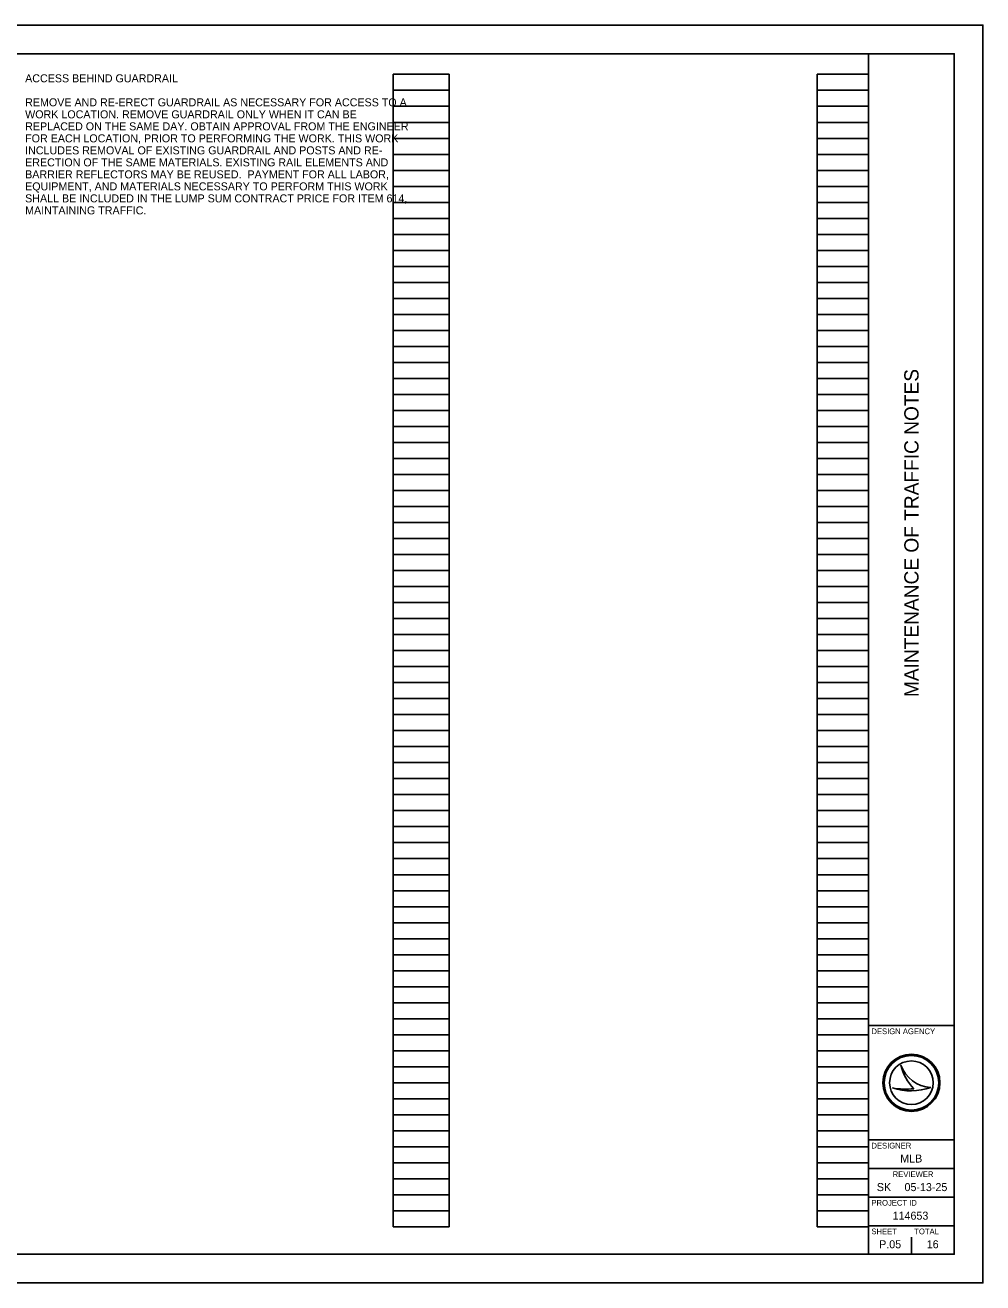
# Model space of a CAD drawing. Extents: x 0 to 34, y 0 to 22.
# Drawn here: x 17.24 to 34, y 0 to 22 of the extents above; entities that cross this region are included whole.
import ezdxf

# ---------------------------------------------------------------- set-up
doc = ezdxf.new("R2010")
doc.units = 0
for name, color, linetype in [('SH_Border', 7, 'Continuous'), ('SH_Cut_Line', 7, 'Continuous'), ('SH_Data', 7, 'Continuous'), ('SH_Text', 7, 'Continuous')]:
    doc.layers.add(name, color=color, linetype=linetype)

msp = doc.modelspace()

# ---------------------------------------------------------------- linework, layer by layer
at = {"layer": 'SH_Border'}
for p, q in [((32, 0.5), (32, 21.5)), ((32, 4.5), (33.5, 4.5)), ((32, 2.5), (33.5, 2.5)), ((32, 2), (33.5, 2)), ((32, 1.5), (33.5, 1.5)), ((32, 1), (33.5, 1))]:
    msp.add_line(p, q, dxfattribs=at)
msp.add_lwpolyline([(1.5, 21.5), (33.5, 21.5), (33.5, 0.5), (1.5, 0.5)], close=True, dxfattribs=at)
at = {"layer": 'SH_Cut_Line'}
msp.add_lwpolyline([(0, 0), (34, 0), (34, 22), (0, 22)], close=True, dxfattribs=at)
at = {"layer": 'SH_Data'}
for p, q in [((23.68, 0.98), (23.68, 21.14)), ((23.68, 21.14), (24.66, 21.14)), ((24.66, 0.98), (24.66, 21.14)), ((31.1, 0.98), (31.1, 21.14)), ((31.1, 21.14), (32, 21.14)), ((32, 0.98), (32, 21.14)), ((23.68, 20.86), (24.66, 20.86)), ((31.1, 20.86), (32, 20.86)), ((23.68, 20.58), (24.66, 20.58)), ((31.1, 20.58), (32, 20.58)), ((23.68, 20.3), (24.66, 20.3)), ((31.1, 20.3), (32, 20.3)), ((23.68, 20.02), (24.66, 20.02)), ((31.1, 20.02), (32, 20.02)), ((23.68, 19.74), (24.66, 19.74)), ((31.1, 19.74), (32, 19.74)), ((23.68, 19.46), (24.66, 19.46)), ((31.1, 19.46), (32, 19.46)), ((23.68, 19.18), (24.66, 19.18)), ((31.1, 19.18), (32, 19.18)), ((23.68, 18.9), (24.66, 18.9)), ((31.1, 18.9), (32, 18.9)), ((23.68, 18.62), (24.66, 18.62)), ((31.1, 18.62), (32, 18.62)), ((23.68, 18.34), (24.66, 18.34)), ((31.1, 18.34), (32, 18.34)), ((23.68, 18.06), (24.66, 18.06)), ((31.1, 18.06), (32, 18.06)), ((23.68, 17.78), (24.66, 17.78)), ((31.1, 17.78), (32, 17.78)), ((23.68, 17.5), (24.66, 17.5)), ((31.1, 17.5), (32, 17.5)), ((23.68, 17.22), (24.66, 17.22)), ((31.1, 17.22), (32, 17.22)), ((23.68, 16.94), (24.66, 16.94)), ((31.1, 16.94), (32, 16.94)), ((23.68, 16.66), (24.66, 16.66)), ((31.1, 16.66), (32, 16.66)), ((23.68, 16.38), (24.66, 16.38)), ((31.1, 16.38), (32, 16.38)), ((23.68, 16.1), (24.66, 16.1)), ((31.1, 16.1), (32, 16.1)), ((23.68, 15.82), (24.66, 15.82)), ((31.1, 15.82), (32, 15.82)), ((23.68, 15.54), (24.66, 15.54)), ((31.1, 15.54), (32, 15.54)), ((23.68, 15.26), (24.66, 15.26)), ((31.1, 15.26), (32, 15.26)), ((23.68, 14.98), (24.66, 14.98)), ((31.1, 14.98), (32, 14.98)), ((23.68, 14.7), (24.66, 14.7)), ((31.1, 14.7), (32, 14.7)), ((23.68, 14.42), (24.66, 14.42)), ((31.1, 14.42), (32, 14.42)), ((23.68, 14.14), (24.66, 14.14)), ((31.1, 14.14), (32, 14.14)), ((23.68, 13.86), (24.66, 13.86)), ((31.1, 13.86), (32, 13.86)), ((23.68, 13.58), (24.66, 13.58)), ((31.1, 13.58), (32, 13.58)), ((23.68, 13.3), (24.66, 13.3)), ((31.1, 13.3), (32, 13.3)), ((23.68, 13.02), (24.66, 13.02)), ((31.1, 13.02), (32, 13.02)), ((23.68, 12.74), (24.66, 12.74)), ((31.1, 12.74), (32, 12.74)), ((23.68, 12.46), (24.66, 12.46)), ((31.1, 12.46), (32, 12.46)), ((23.68, 12.18), (24.66, 12.18)), ((31.1, 12.18), (32, 12.18)), ((23.68, 11.9), (24.66, 11.9)), ((31.1, 11.9), (32, 11.9)), ((23.68, 11.62), (24.66, 11.62)), ((31.1, 11.62), (32, 11.62)), ((23.68, 11.34), (24.66, 11.34)), ((31.1, 11.34), (32, 11.34)), ((23.68, 11.06), (24.66, 11.06)), ((31.1, 11.06), (32, 11.06)), ((23.68, 10.78), (24.66, 10.78)), ((31.1, 10.78), (32, 10.78)), ((23.68, 10.5), (24.66, 10.5)), ((31.1, 10.5), (32, 10.5)), ((23.68, 10.22), (24.66, 10.22)), ((31.1, 10.22), (32, 10.22)), ((23.68, 9.94), (24.66, 9.94)), ((31.1, 9.94), (32, 9.94)), ((23.68, 9.66), (24.66, 9.66)), ((31.1, 9.66), (32, 9.66)), ((23.68, 9.38), (24.66, 9.38)), ((31.1, 9.38), (32, 9.38)), ((23.68, 9.1), (24.66, 9.1)), ((31.1, 9.1), (32, 9.1)), ((23.68, 8.82), (24.66, 8.82)), ((31.1, 8.82), (32, 8.82)), ((23.68, 8.54), (24.66, 8.54)), ((31.1, 8.54), (32, 8.54)), ((23.68, 8.26), (24.66, 8.26)), ((31.1, 8.26), (32, 8.26)), ((23.68, 7.98), (24.66, 7.98)), ((31.1, 7.98), (32, 7.98)), ((23.68, 7.7), (24.66, 7.7)), ((31.1, 7.7), (32, 7.7)), ((23.68, 7.42), (24.66, 7.42)), ((31.1, 7.42), (32, 7.42)), ((23.68, 7.14), (24.66, 7.14)), ((31.1, 7.14), (32, 7.14)), ((23.68, 6.86), (24.66, 6.86)), ((31.1, 6.86), (32, 6.86)), ((23.68, 6.58), (24.66, 6.58)), ((31.1, 6.58), (32, 6.58)), ((23.68, 6.3), (24.66, 6.3)), ((31.1, 6.3), (32, 6.3)), ((23.68, 6.02), (24.66, 6.02)), ((31.1, 6.02), (32, 6.02)), ((23.68, 5.74), (24.66, 5.74)), ((31.1, 5.74), (32, 5.74)), ((23.68, 5.46), (24.66, 5.46)), ((31.1, 5.46), (32, 5.46)), ((23.68, 5.18), (24.66, 5.18)), ((31.1, 5.18), (32, 5.18)), ((23.68, 4.9), (24.66, 4.9)), ((31.1, 4.9), (32, 4.9)), ((23.68, 4.62), (24.66, 4.62)), ((31.1, 4.62), (32, 4.62)), ((23.68, 4.34), (24.66, 4.34)), ((31.1, 4.34), (32, 4.34)), ((23.68, 4.06), (24.66, 4.06)), ((31.1, 4.06), (32, 4.06)), ((23.68, 3.78), (24.66, 3.78)), ((31.1, 3.78), (32, 3.78)), ((32.567, 3.81), (32.567, 3.81)), ((23.68, 3.5), (24.66, 3.5)), ((31.1, 3.5), (32, 3.5)), ((32.417, 3.41), (32.417, 3.41)), ((32.75, 3.5), (32.75, 3.5)), ((33.087, 3.419), (33.087, 3.419)), ((23.68, 3.22), (24.66, 3.22)), ((31.1, 3.22), (32, 3.22)), ((23.68, 2.94), (24.66, 2.94)), ((31.1, 2.94), (32, 2.94)), ((23.68, 2.66), (24.66, 2.66)), ((31.1, 2.66), (32, 2.66)), ((23.68, 2.38), (24.66, 2.38)), ((31.1, 2.38), (32, 2.38)), ((23.68, 2.1), (24.66, 2.1)), ((31.1, 2.1), (32, 2.1)), ((23.68, 1.82), (24.66, 1.82)), ((31.1, 1.82), (32, 1.82)), ((23.68, 1.54), (24.66, 1.54)), ((31.1, 1.54), (32, 1.54)), ((23.68, 1.26), (24.66, 1.26)), ((31.1, 1.26), (32, 1.26)), ((23.68, 0.98), (24.66, 0.98)), ((31.1, 0.98), (32, 0.98)), ((32.375, 0.675), (32.375, 0.675)), ((32.75, 0.5), (32.75, 0.8))]:
    msp.add_line(p, q, dxfattribs=at)
for radius in [0.5, 0.477, 0.477, 0.382]:
    msp.add_circle((32.75, 3.5), radius, dxfattribs=at)
for centre, radius, start, end in [((33.116, 3.998), 0.58, 198.9257, 198.9319), ((33.347, 3.97), 0.796, 191.6379, 191.6421), ((33.116, 3.998), 0.58, 198.9319, 267.1657), ((33.347, 3.97), 0.796, 191.6421, 226.0947), ((32.739, 4.37), 1.013, 251.4576, 290.0832), ((32.648, 4.654), 1.266, 259.4964, 259.4995), ((32.739, 4.37), 1.013, 251.4527, 251.4576), ((32.648, 4.654), 1.266, 259.4995, 276.6672)]:
    msp.add_arc(centre, radius, start, end, dxfattribs=at)

# ---------------------------------------------------------------- texts
msp.add_text('MAINTENANCE OF TRAFFIC NOTES', height=0.25, rotation=90, dxfattribs=at).set_placement((32.875, 10.247))
for s, height, p in [('DESIGN AGENCY', 0.1, (32.05, 4.35)), ('DESIGNER', 0.1, (32.05, 2.35)), ('MLB', 0.14, (32.554, 2.105)), ('REVIEWER', 0.1, (32.422, 1.85)), ('SK', 0.14, (32.145, 1.605)), ('05-13-25', 0.14, (32.629, 1.605)), ('PROJECT ID', 0.1, (32.05, 1.35)), ('114653', 0.14, (32.421, 1.105)), ('SHEET', 0.1, (32.05, 0.85)), ('TOTAL', 0.1, (32.8, 0.85)), ('P.05', 0.14, (32.185, 0.605)), ('16', 0.14, (33.018, 0.605))]:
    msp.add_text(s, height=height, dxfattribs=at).set_placement(p)
at = {"layer": 'SH_Text'}
for s, p in [('ACCESS BEHIND GUARDRAIL', (17.24, 21)), ('REMOVE AND RE-ERECT GUARDRAIL AS NECESSARY FOR ACCESS TO A ', (17.24, 20.58)), ('WORK LOCATION. REMOVE GUARDRAIL ONLY WHEN IT CAN BE ', (17.24, 20.37)), ('REPLACED ON THE SAME DAY. OBTAIN APPROVAL FROM THE ENGINEER ', (17.24, 20.16)), ('FOR EACH LOCATION, PRIOR TO PERFORMING THE WORK. THIS WORK ', (17.24, 19.95)), ('INCLUDES REMOVAL OF EXISTING GUARDRAIL AND POSTS AND RE-', (17.24, 19.74)), ('ERECTION OF THE SAME MATERIALS. EXISTING RAIL ELEMENTS AND ', (17.24, 19.53)), ('BARRIER REFLECTORS MAY BE REUSED.  PAYMENT FOR ALL LABOR, ', (17.24, 19.32)), ('EQUIPMENT, AND MATERIALS NECESSARY TO PERFORM THIS WORK ', (17.24, 19.11)), ('SHALL BE INCLUDED IN THE LUMP SUM CONTRACT PRICE FOR ITEM 614, ', (17.24, 18.9)), ('MAINTAINING TRAFFIC.', (17.24, 18.69))]:
    msp.add_text(s, height=0.14, dxfattribs=at).set_placement(p)

doc.saveas('drawing.dxf')
